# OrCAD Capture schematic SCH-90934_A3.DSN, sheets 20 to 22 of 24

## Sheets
20 C-06 CPU IO/PHY: size C
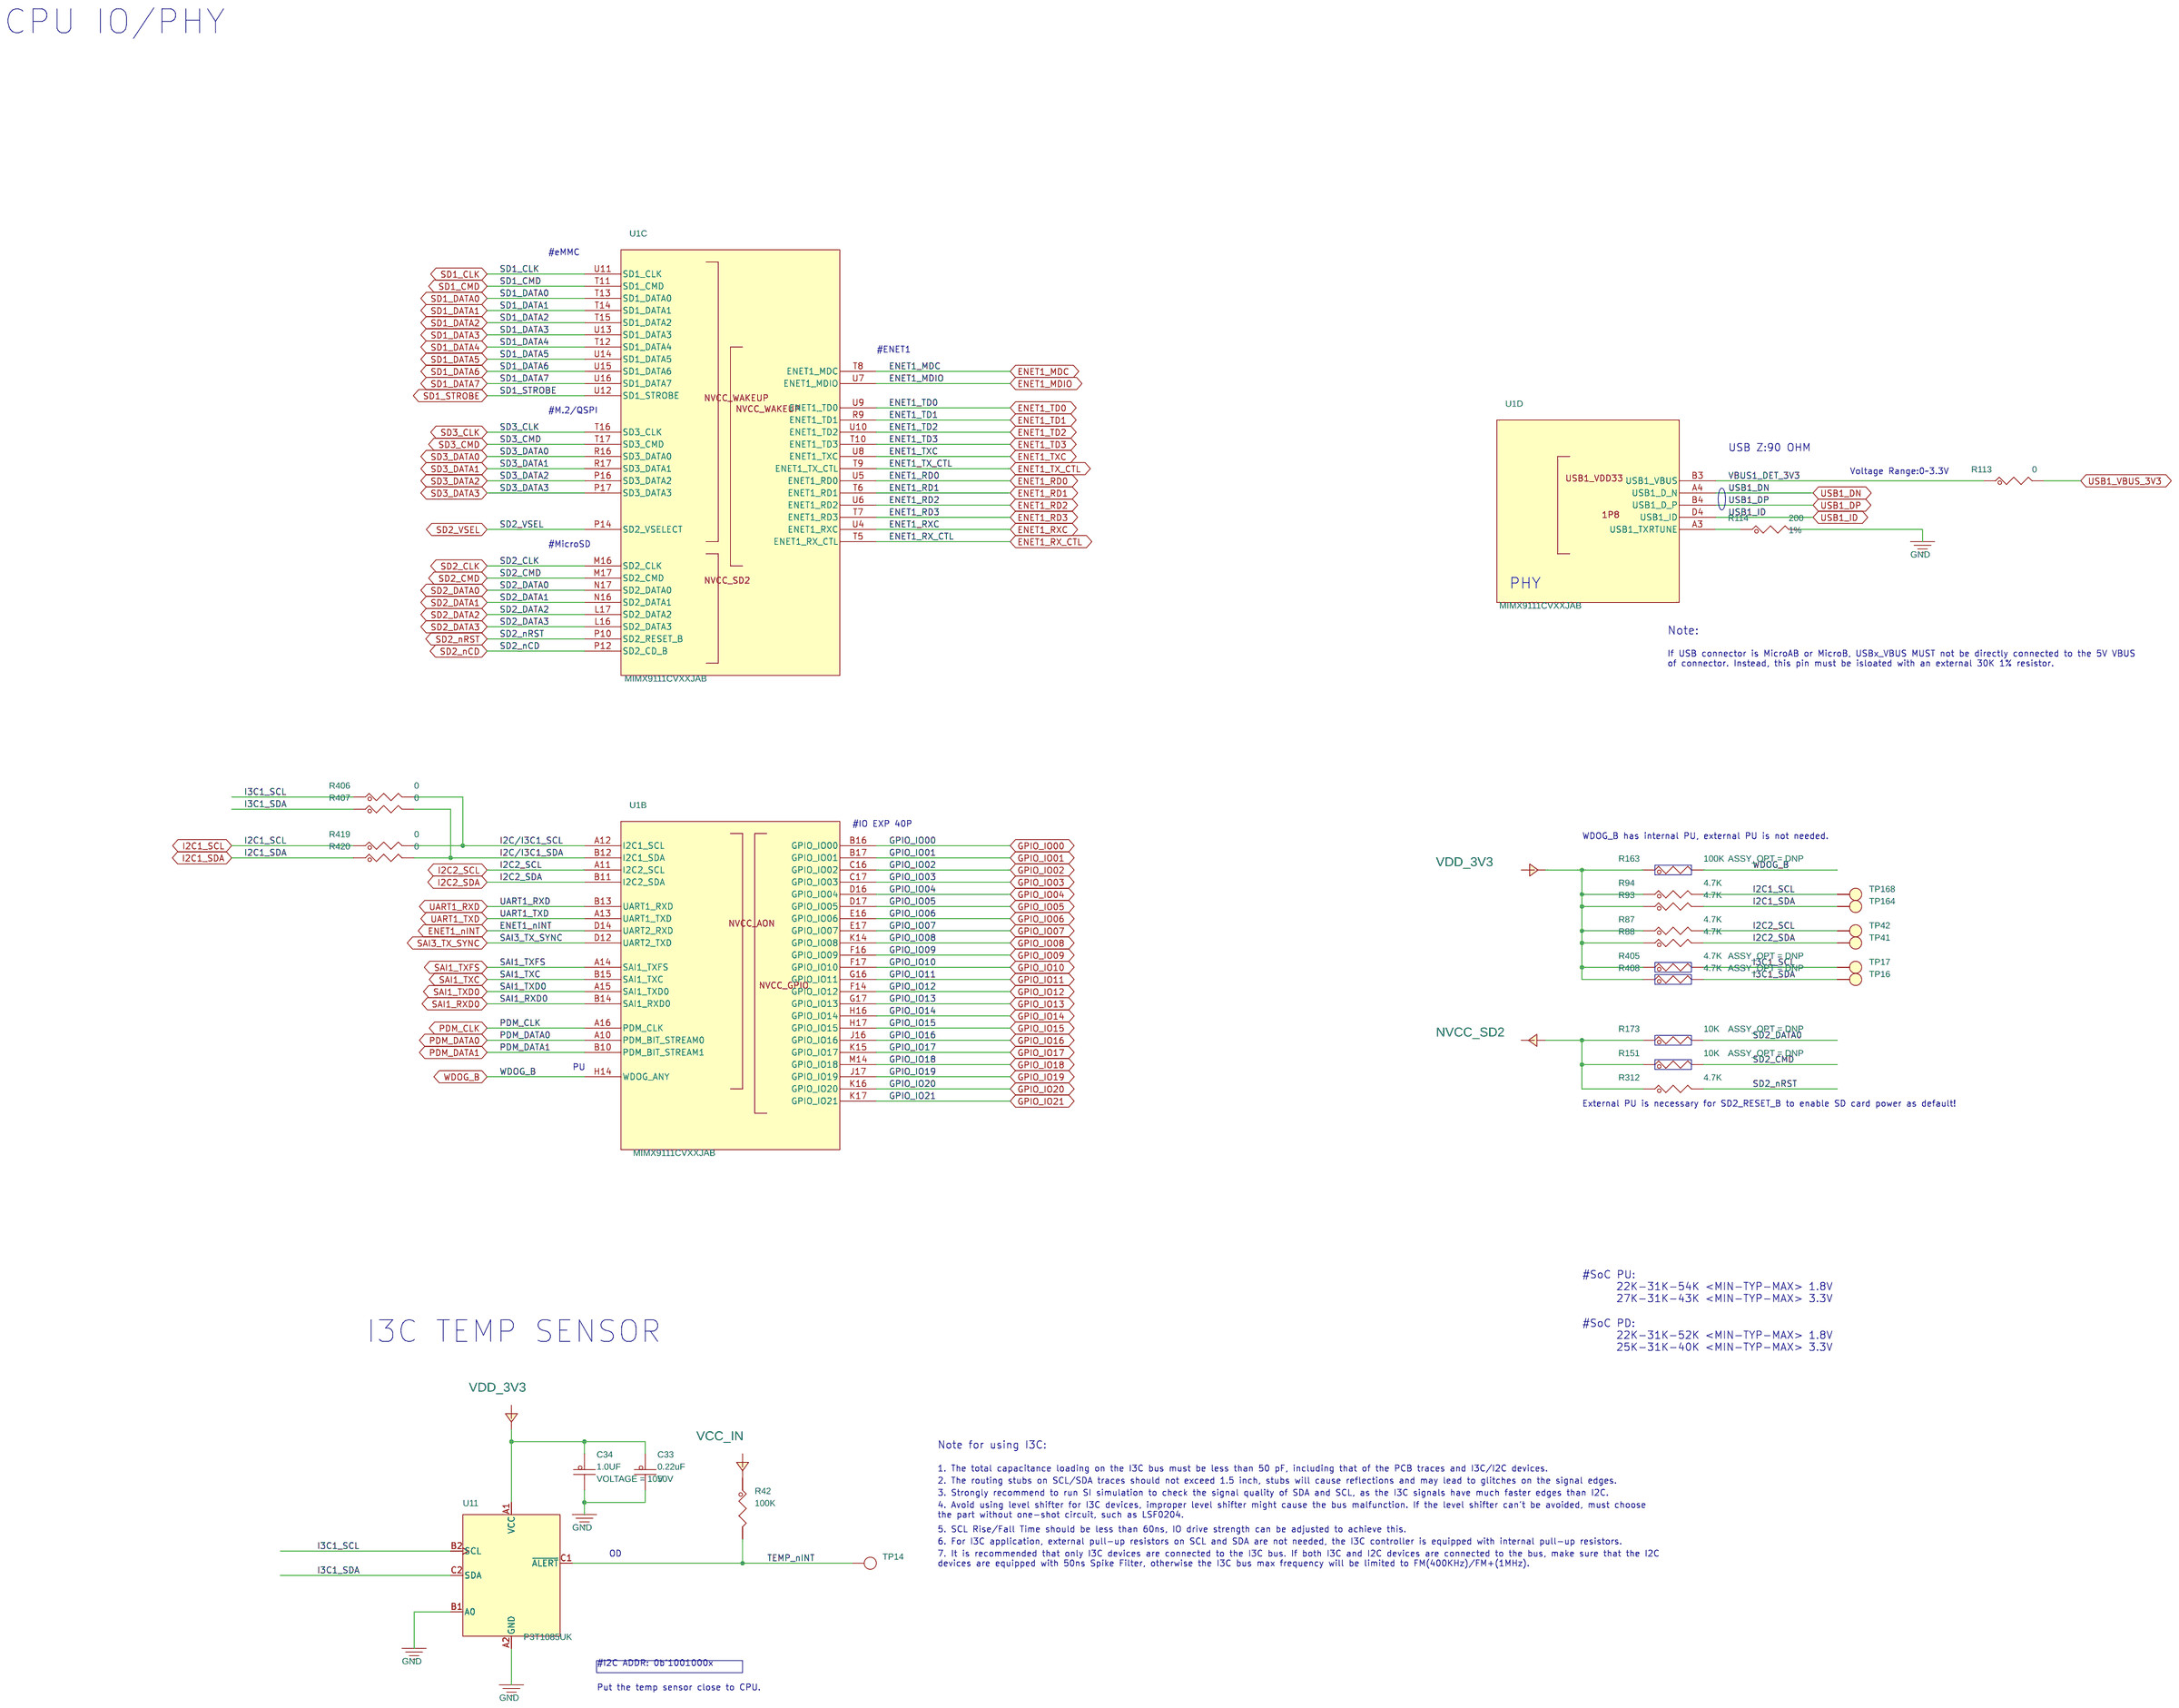
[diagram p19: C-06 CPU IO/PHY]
21 C-17 CAN/Ext RTC: size A3
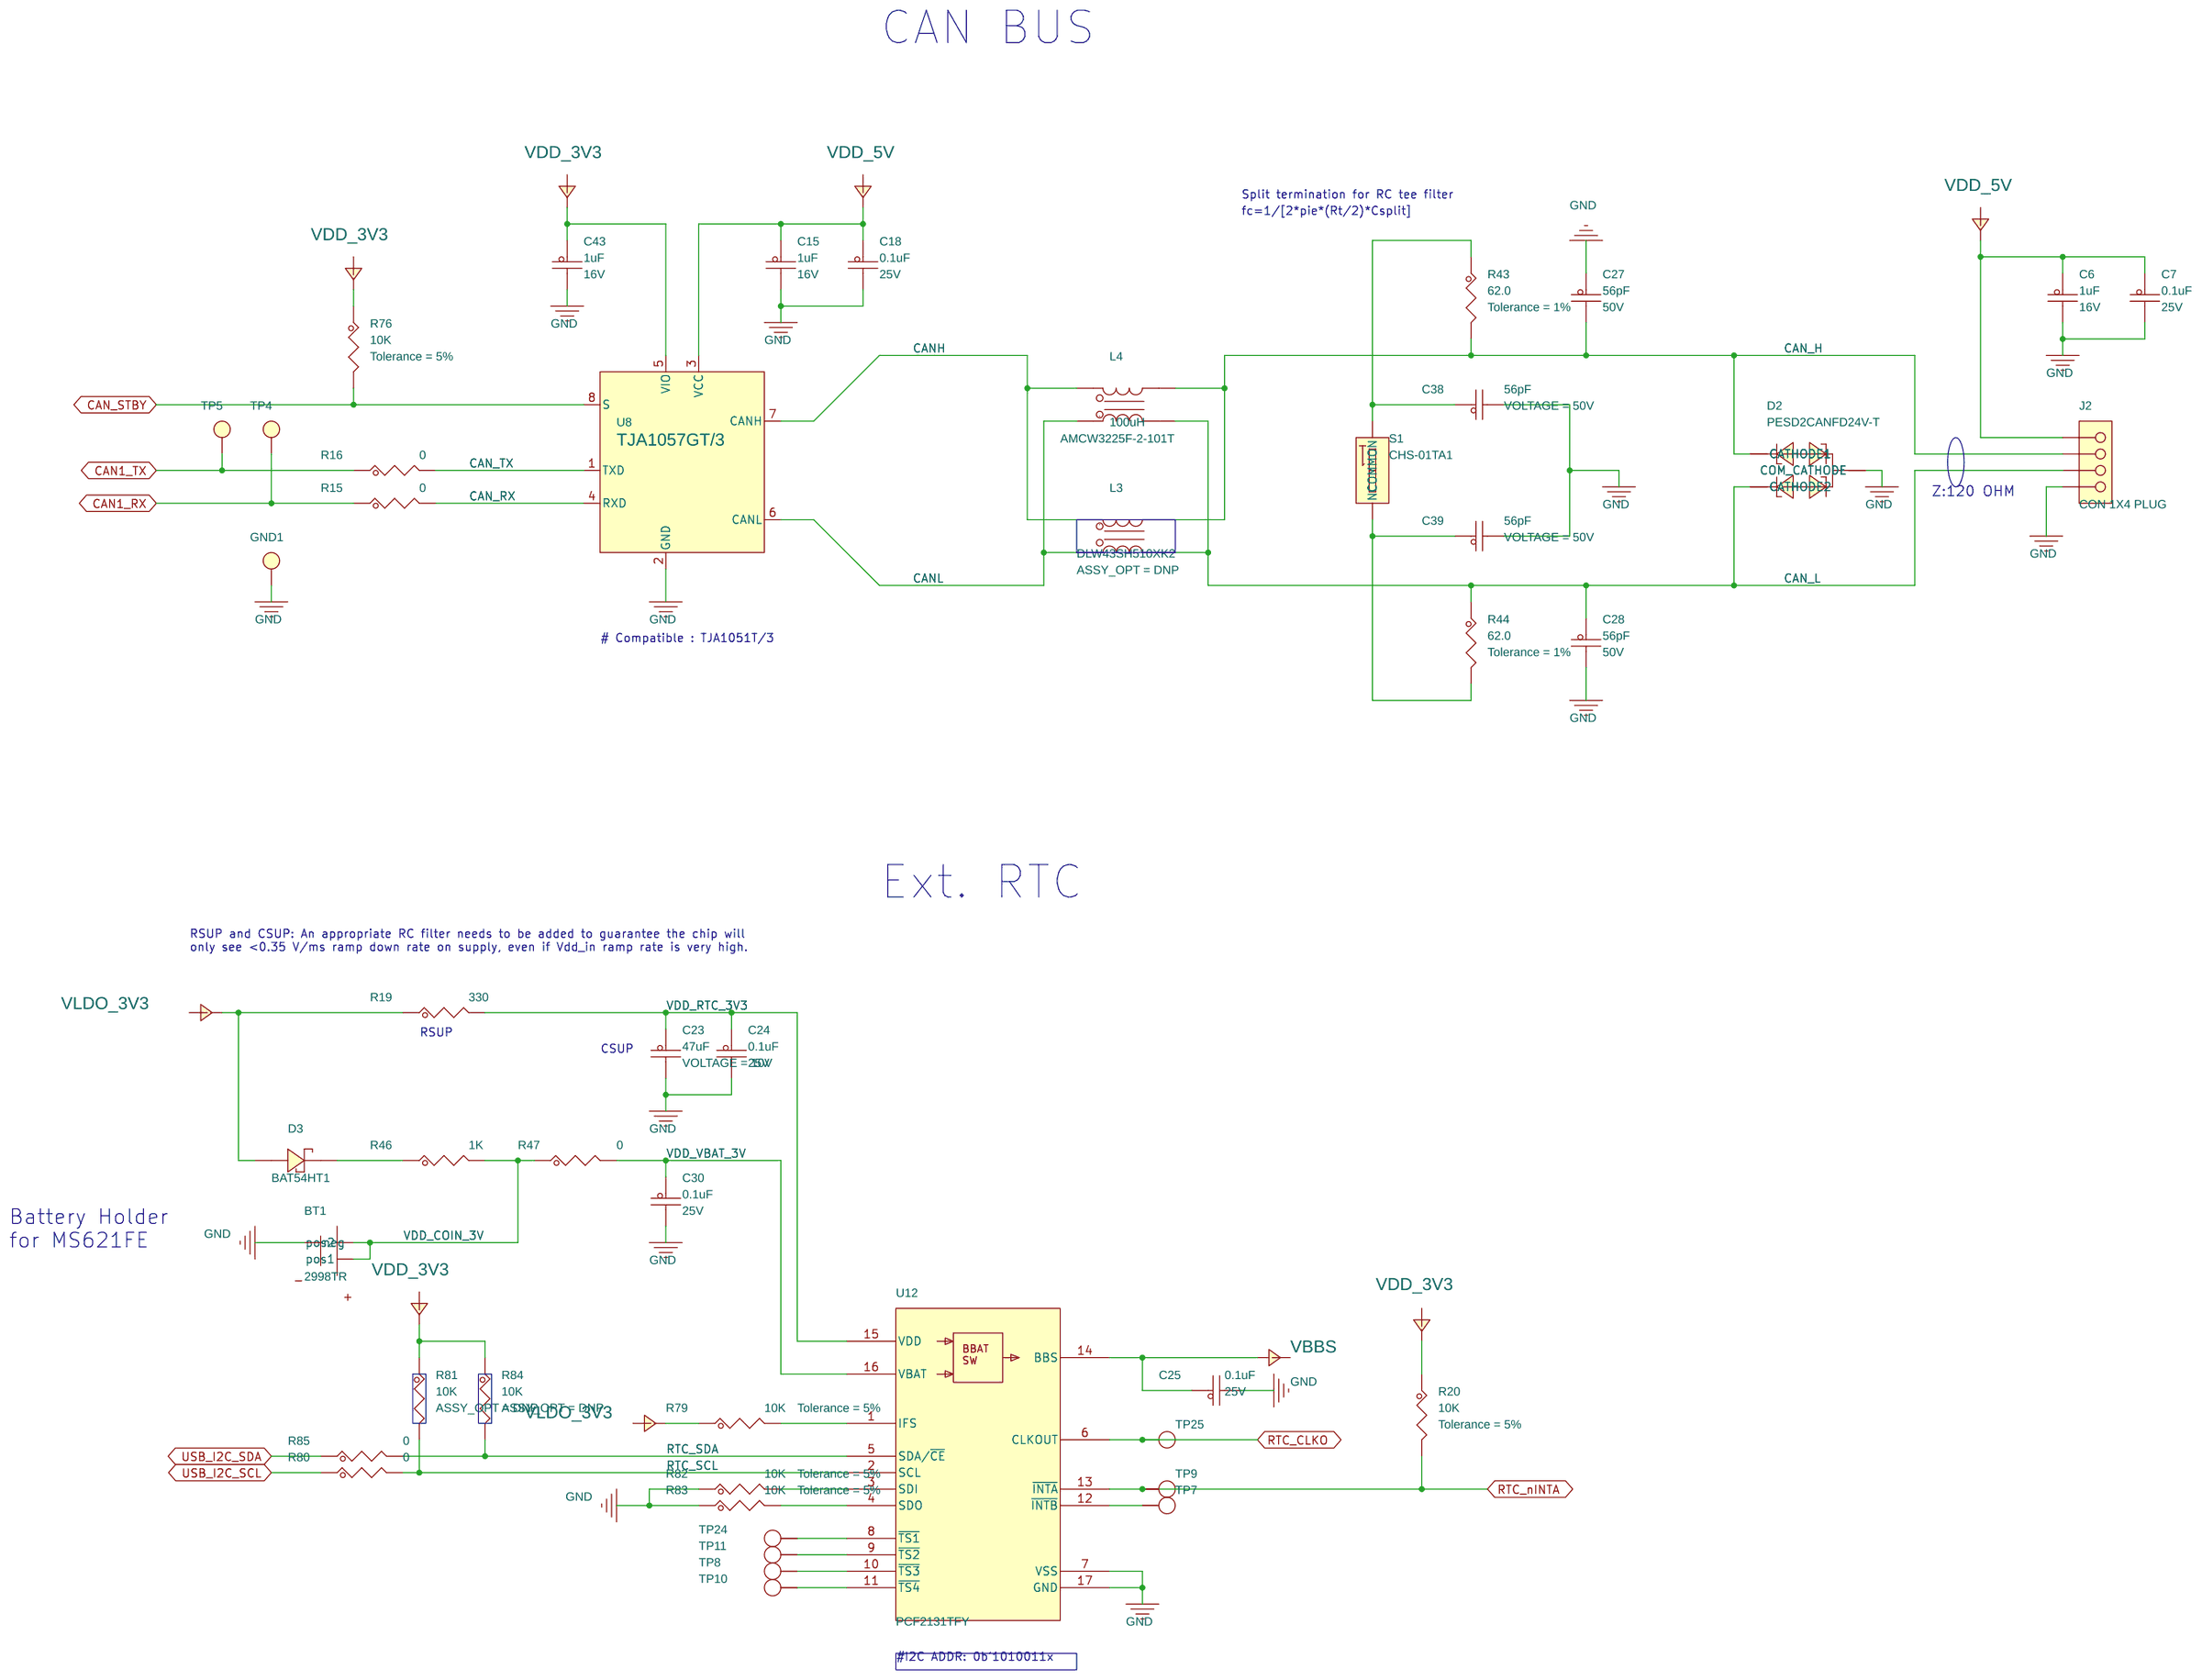
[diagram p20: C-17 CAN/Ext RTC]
22 C-15 M.2 WIFI/BT: size C
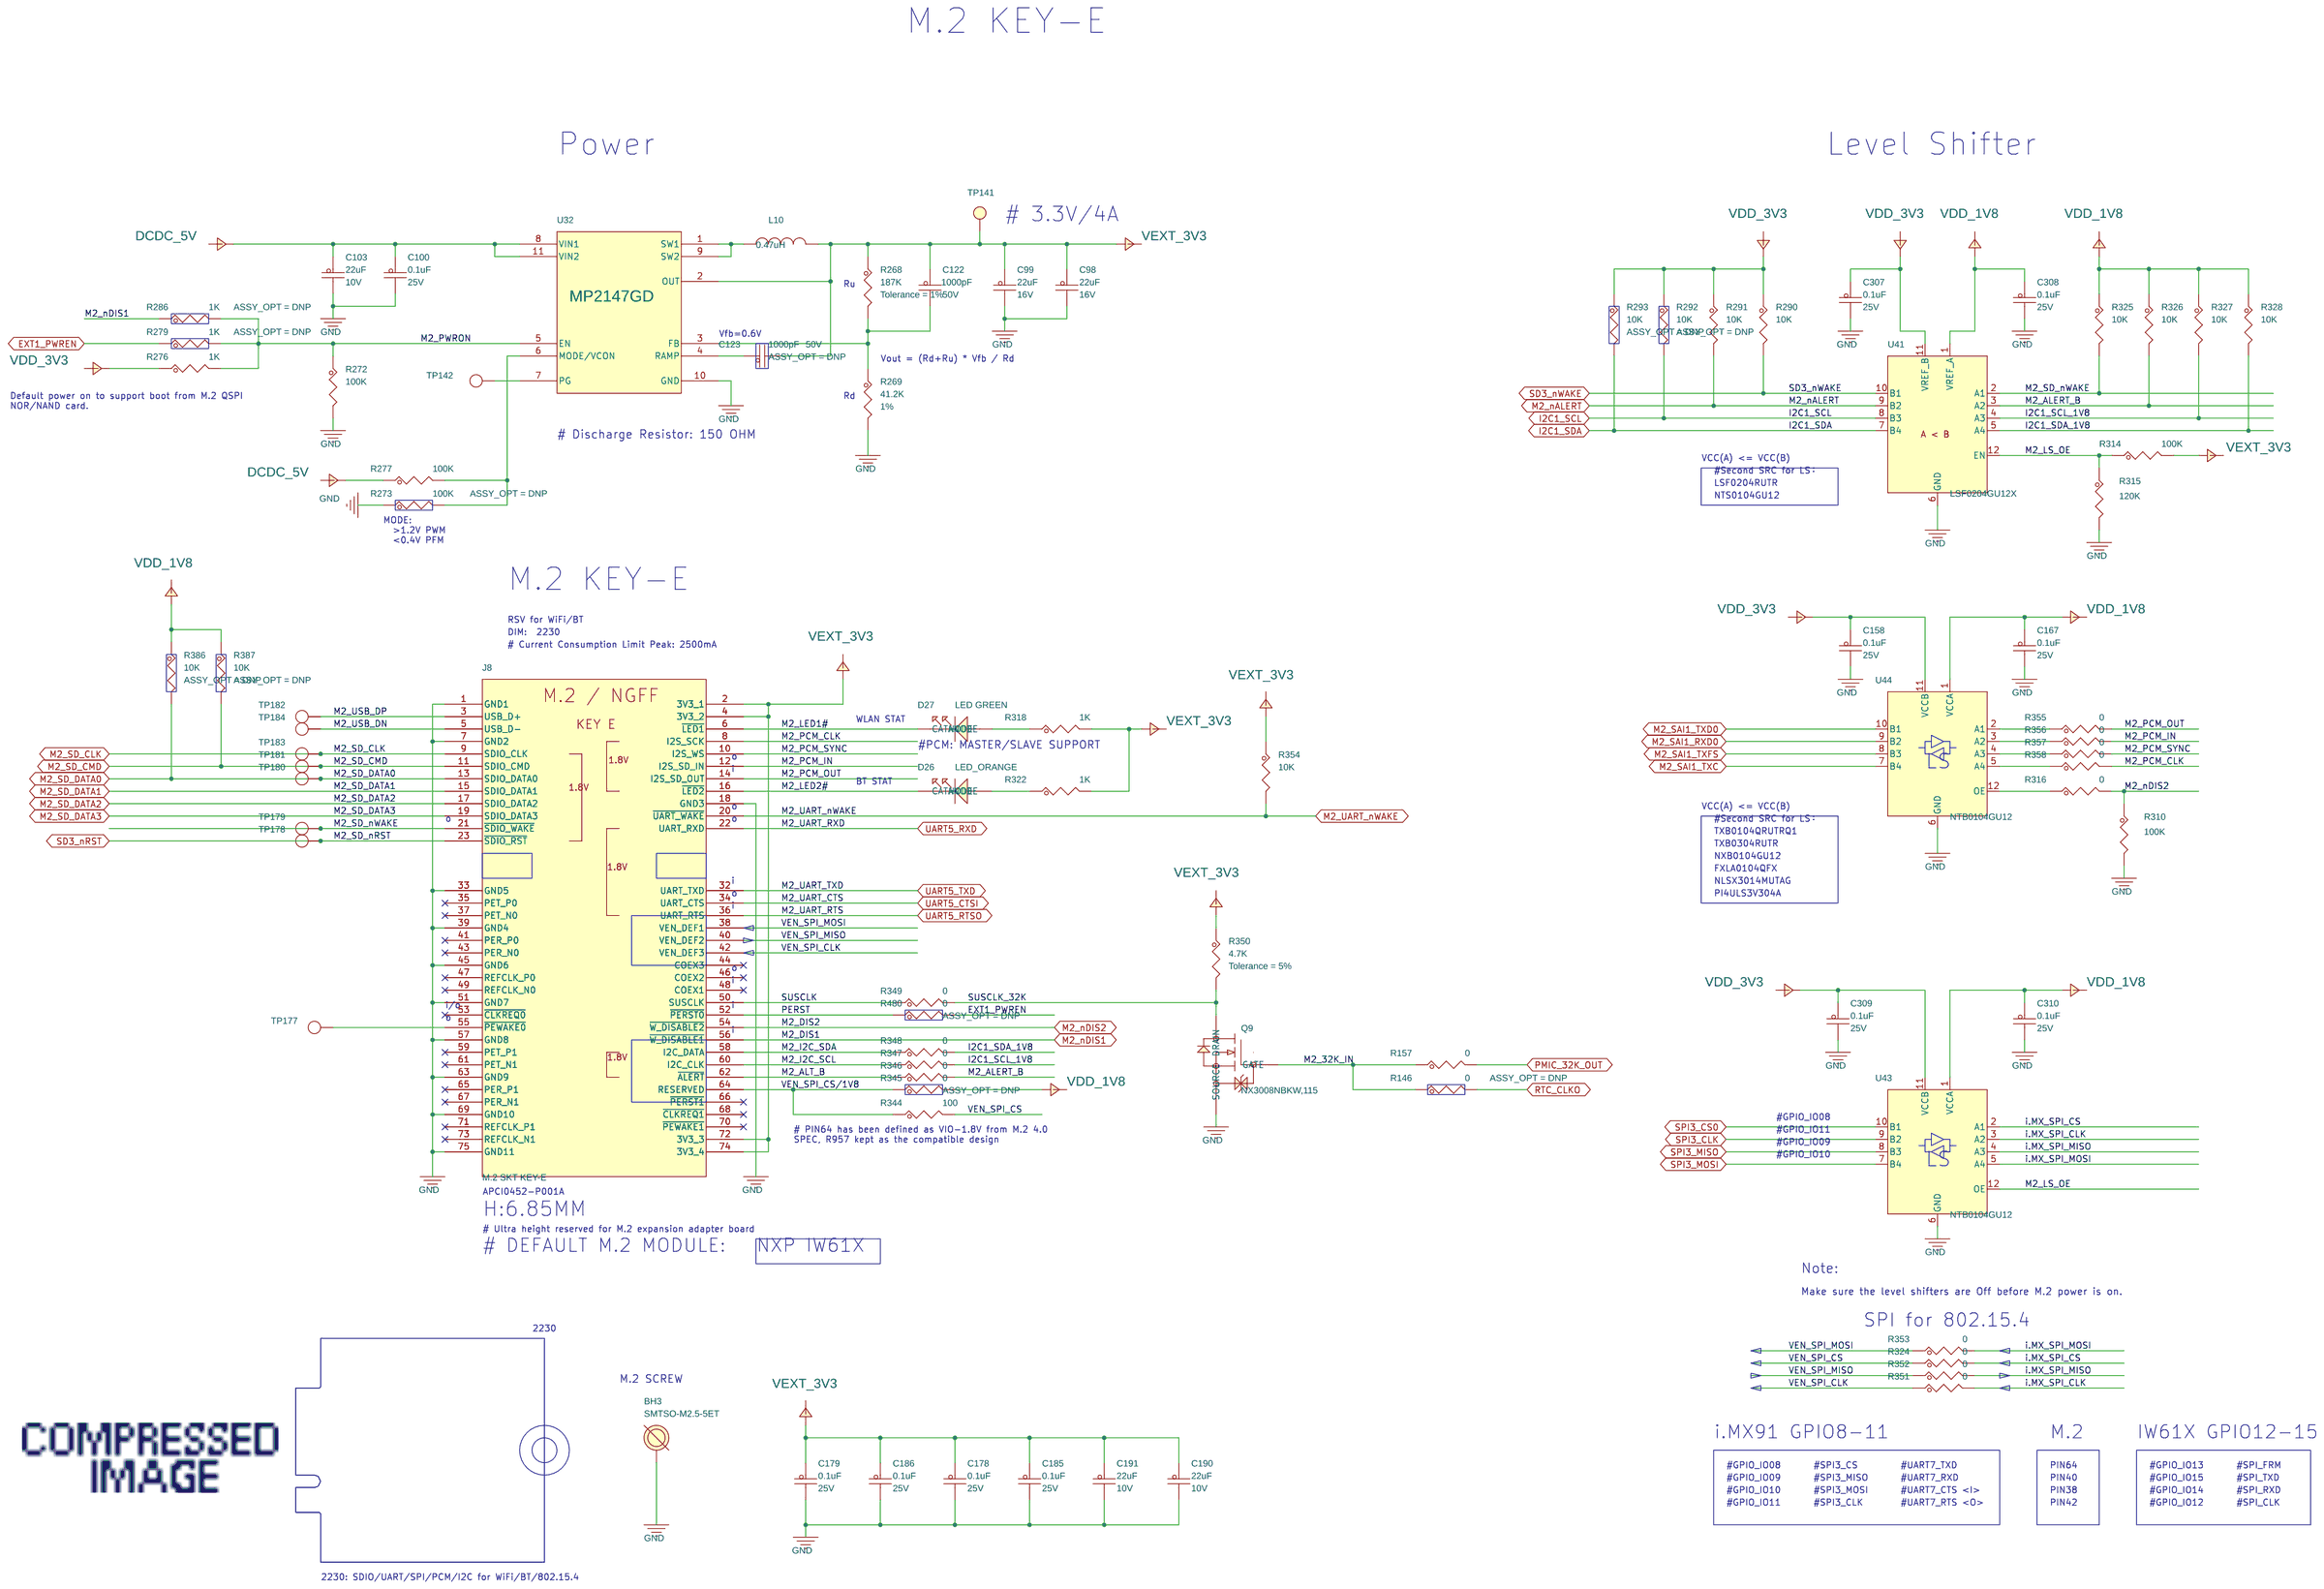
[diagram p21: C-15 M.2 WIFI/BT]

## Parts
sheet C-06 CPU IO/PHY
C33  0.22uF  [CC0402_25]
C34  1.0UF  [CC0402_25]
R42  100K  [0402_CC]
R87  4.7K  [0402_CC]
R88  4.7K  [0402_CC]
R93  4.7K  [0402_CC]
R94  4.7K  [0402_CC]
R113  0  [0201_CC]
R114  200  [0201_CC]
R151  10K  [0402_CC]
R163  100K  [0402_CC]
R173  10K  [0402_CC]
R312  4.7K  [0402_CC]
R405  4.7K  [0402_CC]
R406  0  [RC0402_25]
R407  0  [RC0402_25]
R408  4.7K  [0402_CC]
R419  0  [RC0402_25]
R420  0  [RC0402_25]
TP14  TPAD_020  [tpad_020]
TP16  TP_35MIL  [testpoint_35mil]
TP17  TP_35MIL  [testpoint_35mil]
TP41  TP_35MIL  [testpoint_35mil]
TP42  TP_35MIL  [testpoint_35mil]
TP164  TP_35MIL  [testpoint_35mil]
TP168  TP_35MIL  [testpoint_35mil]
U11  P3T1085UK  [wlcsp6_0p4_0p84x1p18]
sheet C-07 CPU MISC
U1  MIMX9111CVXXJAB  [pbga208_0p5_9x9mm_sm]  (sections A,B,C,D,E,F)
sheet C-15 M.2 WIFI/BT
BH3  SMTSO-M2.5-5ET  [mh244-166t_202h]
C98  22uF  [CC0805_OV]
C99  22uF  [CC0805_OV]
C100  0.1uF  [CC0402_25]
C103  22uF  [CC0603]
C122  1000pF  [CC0402_25]
C123  1000pF  [CC0402_25]
C158  0.1uF  [CC0402_25]
C167  0.1uF  [CC0402_25]
C178  0.1uF  [CC0402_25]
C179  0.1uF  [CC0402_25]
C185  0.1uF  [CC0402_25]
C186  0.1uF  [CC0402_25]
C190  22uF  [CC0603]
C191  22uF  [CC0603]
C307  0.1uF  [CC0402_25]
C308  0.1uF  [CC0402_25]
C309  0.1uF  [CC0402_25]
C310  0.1uF  [CC0402_25]
D26  LED_ORANGE  [led_0603_11mil]
D27  LED GREEN  [LED_0603]
J8  M.2 SKT KEY-E  [con67_0p5_type-e_22x7p3_ra_270h]
L10  0.47uH  [ind_sph2520]
Q9  NX3008NBKW,115  [sc70_3]
R146  0  [0402_CC]
R157  0  [0402_CC]
R268  187K  [0402_CC]
R269  41.2K  [RC0402_25]
R272  100K  [0402_CC]
R273  100K  [0402_CC]
R276  1K  [0402_CC]
R277  100K  [0402_CC]
R279  1K  [0402_CC]
R286  1K  [0402_CC]
R290  10K  [0402_CC]
R291  10K  [0402_CC]
R292  10K  [0402_CC]
R293  10K  [0402_CC]
R310  100K  [0402_CC]
R314  100K  [0402_CC]
R315  120K  [0402_CC]
R316  0  [0402_CC]
R318  1K  [0402_CC]
R322  1K  [0402_CC]
R324  0  [0402_CC]
R325  10K  [0402_CC]
R326  10K  [0402_CC]
R327  10K  [0402_CC]
R328  10K  [0402_CC]
R344  100  [RC0402_25]
R345  0  [0402_CC]
R346  0  [0402_CC]
R347  0  [0402_CC]
R348  0  [0402_CC]
R349  0  [0402_CC]
R350  4.7K  [RC0402_25]
R351  0  [0402_CC]
R352  0  [0402_CC]
R353  0  [0402_CC]
R354  10K  [0402_CC]
R355  0  [0402_CC]
R356  0  [0402_CC]
R357  0  [0402_CC]
R358  0  [0402_CC]
R386  10K  [0402_CC]
R387  10K  [0402_CC]
R480  0  [0402_CC]
TP141  TP_35MIL  [testpoint_35mil]
TP142  TPAD_020  [tpad_020]
TP177  TPAD_020  [tpad_020]
TP178  TPAD_020  [tpad_020]
TP179  TPAD_020  [tpad_020]
TP180  TPAD_020  [tpad_020]
TP181  TPAD_020  [tpad_020]
TP182  TPAD_020  [tpad_020]
TP183  TPAD_020  [tpad_020]
TP184  TPAD_020  [tpad_020]
U32  MP2147GD  [qfn12_0p5_2x3mm_ep]
U41  LSF0204GU12X  [uqfn12_1p7x2mm]
U43  NTB0104GU12  [xqfn12_0p4_1p8x2p1]
U44  NTB0104GU12  [xqfn12_0p4_1p8x2p1]
sheet C-17 CAN/Ext RTC
BT1  2998TR  [batt_6p8mm_sm]
C6  1uF  [CC0402_25]
C7  0.1uF  [CC0402_25]
C15  1uF  [CC0402_25]
C18  0.1uF  [CC0402_25]
C23  47uF  [0805_CC]
C24  0.1uF  [CC0402_25]
C25  0.1uF  [CC0402_25]
C27  56pF  [CC0402_25]
C28  56pF  [CC0402_25]
C30  0.1uF  [CC0402_25]
C38  56pF  [CC0402_25]
C39  56pF  [CC0402_25]
C43  1uF  [CC0402_25]
D2  PESD2CANFD24V-T  [sot23_a]
D3  BAT54HT1  [SOD323]
GND1  TP_35MIL  [testpoint_35mil]
J2  CON 1X4 PLUG  [con1x4_2mm_th_303h]
L3  DLW43SH510XK2  [IND_DLW43]
L4  100uH  [ind4_amcw3225_smt]
R15  0  [0402_CC]
R16  0  [0402_CC]
R19  330  [RC0402_25]
R20  10K  [0402_CC]
R43  62.0  [0603_CC]
R44  62.0  [0603_CC]
R46  1K  [0402_CC]
R47  0  [0402_CC]
R76  10K  [0402_CC]
R79  10K  [0402_CC]
R80  0  [0402_CC]
R81  10K  [0402_CC]
R82  10K  [0402_CC]
R83  10K  [0402_CC]
R84  10K  [0402_CC]
R85  0  [0402_CC]
S1  CHS-01TA1  [sw_2p8x5p7_sm]
TP4  TP_35MIL  [testpoint_35mil]
TP5  TP_35MIL  [testpoint_35mil]
TP7  TPAD_020  [tpad_020]
TP8  TPAD_020  [tpad_020]
TP9  TPAD_020  [tpad_020]
TP10  TPAD_020  [tpad_020]
TP11  TPAD_020  [tpad_020]
TP24  TPAD_020  [tpad_020]
TP25  TPAD_020  [tpad_020]
U8  TJA1057GT/3  [SO8_1P27_4X5]
U12  PCF2131TFY  [so16_0p5_3p5x4p5_mm]

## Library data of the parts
C33 = CAP_NP: CAP CER 0.22uF 50V 10% X5R 0402; AGILE_PN: 150-79999; CAD_APPROVED: Yes; FPLIST: CC0402_25,CC0402_HD,0402_CC; HEIGHT: 0.55MM; MFG_NAME01: TAIYO YUDEN; MFG_PN01: UMK105BJ224KV-F; Package Size: 0402; ROHS: Yes; Rated Voltage: 50V; Temp Range: -55C to +85C; Temp_Range: -55°C to +85°C; Tolerance: 10%; VOLTAGE: 50V
C34 = CAP_NP: CAP CER 1.0UF 10V 10% X5R 0402; AGILE_PN: 150-75772; CAD_APPROVED: Yes; FPLIST: CC0402_25,CC0402_HD,0402_CC; HEIGHT: 0.6MM; MFG_NAME01: YAGEO AMERICA; MFG_PN01: CC0402KRX5R6BB105; Package Size: 0402; ROHS: Yes; Rated Voltage: 10V; SIGNAL_MODEL: DEFAULT_CAPACITOR_1e+06pF_2_1; TOL: 10%; Temp Range: -55C to +85C; Tolerance: 10%; VOLTAGE: 10V; voltage rating: 10V
R42 = RES: RES MF 100K 1/16W 5% 0402; AGILE_PN: 470-75597; CAD_APPROVED: Yes; FPLIST: RC0402_25,RC0402_HD,0402_CC; HEIGHT: 0.40 MM; MFG_NAME01: VENKEL COMPANY; MFG_PN01: CR0402-16W-104JT; ROHS: Yes; Temp Range: -55C to +155C; Tolerance: 5%; VOLTAGE: 50V
R87 R88 R93 R94 R312 = RES: RES MF 4.7K 1/10W 5% AEC-Q200 0402; AGILE_PN: 470-82064; CAD_APPROVED: Yes; FPLIST: RC0402_25,RC0402_HD,0402_CC,RC0402_X2; HEIGHT: 0.41mm; MFG_NAME01: KOA SPEER; MFG_PN01: RK73B1ETTP472J; ROHS: Yes; Temp Range: -55C to +155C; Temp_Range: -55C to +155C; Tolerance: 5%; VOLTAGE: 50V
R113 = RES: RES MF ZERO OHM 1/20W -- 0201; AGILE_PN: 470-76631; CAD_APPROVED: Yes; FPLIST: RC0201,0201_CC,RC0201_X2; HEIGHT: 0.30 MM; MFG_NAME01: BOURNS; MFG_PN01: CR0201-J/-000GLF; ROHS: Yes
R114 = RES: RES MF 200 OHM 1/20W 1% 0201; AGILE_PN: 470-82323; CAD_APPROVED: Yes; FPLIST: RC0201,0201_CC; HEIGHT: 0.26MM; MFG_NAME01: YAGEO AMERICA; MFG_PN01: RC0201FR-07200RL; ROHS: Yes; Temp Range: -55°C ~ 125°C; Temp_Range: -55°C ~ 125°C; Tolerance: 1%; VOLTAGE: 25V
R81 R84 R151 R173 R292 R293 R386 R387 = RES: RES MF 10K 1/16W 5% 0402; AGILE_PN: 470-75557; ASSY_OPT: DNP; CAD_APPROVED: Yes; FPLIST: RC0402_25,RC0402_HD,0402_CC; HEIGHT: 0.4 MM; MFG_NAME01: VISHAY INTERTECHNOLOGY; MFG_PN01: CRCW040210K0JNED; ROHS: Yes; Tolerance: 5%
R163 = RES: RES MF 100K 1/16W 5% 0402; AGILE_PN: 470-75597; ASSY_OPT: DNP; CAD_APPROVED: Yes; FPLIST: RC0402_25,RC0402_HD,0402_CC; HEIGHT: 0.40 MM; MFG_NAME01: VENKEL COMPANY; MFG_PN01: CR0402-16W-104JT; ROHS: Yes; Temp Range: -55C to +155C; Tolerance: 5%; VOLTAGE: 50V
R405 R408 = RES: RES MF 4.7K 1/10W 5% AEC-Q200 0402; AGILE_PN: 470-82064; ASSY_OPT: DNP; CAD_APPROVED: Yes; FPLIST: RC0402_25,RC0402_HD,0402_CC,RC0402_X2; HEIGHT: 0.41mm; MFG_NAME01: KOA SPEER; MFG_PN01: RK73B1ETTP472J; ROHS: Yes; Temp Range: -55C to +155C; Temp_Range: -55C to +155C; Tolerance: 5%; VOLTAGE: 50V
R47 R80 R85 R157 R316 R324 R346-R349 R351-R353 R355-R358 R406 R407 R419 R420 = RES: RES MF ZERO OHM 1/16W 5% 0402; AGILE_PN: 470-75394; CAD_APPROVED: Yes; FPLIST: RC0402_25,RC0402_HD,RC0402_X2,0402_CC; HEIGHT: 0.45; MFG_NAME01: YAGEO AMERICA; MFG_PN01: RC0402JR-070RL; ROHS: Yes; Temp Range: -55 to +155C; Tolerance: 5%; VOLTAGE: 1/16W
TP7-TP11 TP14 TP24 TP25 TP142 TP177-TP184 = TESTLOOP: TEST POINT PAD 0.5MM DIA SMT, NO PART TO ORDER; AGILE_PN: 211-77484; ASSY_OPT: DNP; CAD_APPROVED: Yes; HEIGHT: 0.1MM; ROHS: Yes
GND1 TP4 TP5 TP16 TP17 TP41 TP42 TP141 TP164 TP168 = T_POINT_R: TEST POINT PAD .035 SMT, no part to order; AGILE_PN: 510-75618; ASSY_OPT: DNP; CAD_APPROVED: Yes; HEIGHT: 0.1MM; ROHS: Yes
U11 = P3T2108_6P: IC DIG TEMP SENSOR 12BIT I3C/I2C 12.5MHz/3.4MHz 1.4-3.6V WLCSP6; 3D_Mechanical_Footprint_File: http://fcl.am.freescale.net/ALLEGRO/step/wlcsp6_0p4_0p84x1p18.STEP; AGILE_PN: TMP-CIP-12138; HEIGHT: 0.485MM; MFG_NAME01: NXP SEMICONDUCTORS; MFG_PN01: P3T1085UKZ; PRE_APN: 312-83691; ROHS: Yes; Temp Range: -40°C to +125°C; VOLTAGE: 1.4-3.6V
U1 = MIMX9122DVXxLAA_BGA208_A: IC CPU SINGLE CORTEX A55 1.4GHz -- FCPBGA208; 3D_Mechanical_Footprint_File: http://fcl.am.freescale.net/ALLEGRO/step/pbga208_0p5_9x9mm_sm.STEP; AGILE_PN: 330-10031; CAD_APPROVED: Yes; HEIGHT: 1mm; MFG_NAME01: NXP SEMICONDUCTOR; Package Size: FCPBGA208; ROHS: NULL; Temp Range: -40  °C to +105 °C
BH3 = MOUNT_HOLE: FASTENER, STANDOFF M2.5 ROUND FEMALE OD CS L5.13MM; AGILE_PN: 280-77749; CAD_APPROVED: Yes; HEIGHT: 5.13MM; MFG_NAME01: SHENZHEN SINHOO SCIENCE TECHNOLOGY DEVELOPMENT CO.,LTD; ROHS: Yes
C98 C99 = CAP_NP: CAP CER 22UF 16V 20% X5R 0805; 3D_Mechanical_Footprint_File: http://fcl.am.freescale.net/ALLEGRO/step/cc0805_ov.STEP; AGILE_PN: 150-81221; CAD_APPROVED: Yes; FPLIST: CC0805_OV,CC0805,0805_CC; HEIGHT: 1.45MM; MFG_NAME01: TDK Corporation; MFG_PN01: C2012X5R1C226M125AC; Package Size: 0805 (2012 Metric); ROHS: Yes; Rated Voltage: 16V; Temp Range: -55C to +85C; Tolerance: 20%; VOLTAGE: 16V
C7 C18 C24 C30 C100 C158 C167 C178 C179 C185 C186 C307-C310 = CAP_NP: CAP CER 0.1UF 25V 10% X5R 0402; AGILE_PN: 150-78633; CAD_APPROVED: Yes; FPLIST: CC0402_25,CC0402_HD,0402_CC,capc0402_l; HEIGHT: 0.55MM; MFG_NAME01: YAGEO AMERICA; MFG_PN01: CC0402KRX5R8BB104; Package Size: 0402; ROHS: Yes; Rated Voltage: 25V; Temp Range: -55C to +85C; Tolerance: 10%; VOLTAGE: 25V
C103 C190 C191 = CAP_NP: CAP CER 22uF 10V 20% X5R 0603; AGILE_PN: 150-79530; CAD_APPROVED: Yes; FPLIST: CC0603_OV,CC0603,0603_cc_tol; HEIGHT: 1MM; MFG_NAME01: SAMSUNG; MFG_PN01: CL10A226MP7LUNC; Package Size: 0603; ROHS: Yes; Rated Voltage: 10V; SIGNAL_MODEL: DEFAULT_CAPACITOR_2.2e+07pF_2_1; Temp Range: -55C to +85C; Tolerance: 20%; VOLTAGE: 10V; WVDC: 6.3V
C122 = CAP_NP: CAP CER 1000PF 50V 5% C0G 0402; AGILE_PN: 150-76334; CAD_APPROVED: Yes; FPLIST: CC0402_25,CC0402_HD,0402_CC; HEIGHT: 0.55MM; MFG_NAME01: MURATA; MFG_PN01: GRM1555C1H102JA01D; Package Size: 0402; Package Type: 180mm Paper Tape; ROHS: Yes; Rated Voltage: 50V; Temp Range: -55C to +125C; Tolerance: 5%; VOLTAGE: 50V
C123 = CAP_NP: CAP CER 1000PF 50V 5% C0G 0402; AGILE_PN: 150-76334; ASSY_OPT: DNP; CAD_APPROVED: Yes; FPLIST: CC0402_25,CC0402_HD,0402_CC; HEIGHT: 0.55MM; MFG_NAME01: MURATA; MFG_PN01: GRM1555C1H102JA01D; Package Size: 0402; Package Type: 180mm Paper Tape; ROHS: Yes; Rated Voltage: 50V; Temp Range: -55C to +125C; Tolerance: 5%; VOLTAGE: 50V
D26 = LED: LED OR SGL 20MA 0603; 3D_Mechanical_Footprint_File: http://fcl.am.freescale.net/ALLEGRO/step/led_0603_11mil.STEP; AGILE_PN: 370-76572; CAD_APPROVED: Yes; HEIGHT: 0.28; MFG_NAME01: KINGBRIGHT; MFG_PN01: APG1608SEKC/T; ROHS: Yes; Rated Voltage: 2V; Temp Range: -40°C to +85°C; Temp_Range: -40°C to +85°C; VOLTAGE: 2v
D27 = LED: LED GRN SGL 25MA SMT 0603; AGILE_PN: 370-76672; CAD_APPROVED: Yes; HEIGHT: 0.8; MFG_NAME01: DIALIGHT; MFG_PN01: 598-8070-107F; ROHS: Yes; Rated Voltage: 2V; VOLTAGE: 2V
J8 = CON_67_FEMALE_RA_B: CON 67 PCIE M.2 KEY-E RA SMT 0.5MM SP 270H AU; 3D_Mechanical_Footprint_File: http://fcl.am.freescale.net/ALLEGRO/step/con67_0p5_type-e_22x7p3_ra_270h.STEP; AGILE_PN: 211-81337; CAD_APPROVED: Yes; HEIGHT: 6.85; MFG_NAME01: LOTES CO LTD; MFG_PN01: APCI0452-P001A; Package Size: 22.0 x 7.3 x 6.85 mm; Package Type: SMD/SMT; ROHS: Yes
L10 = INDUCTOR: IND PWR 0.47uH@1MHZ 4.7A 20% SMT; AGILE_PN: 180-78647; CAD_APPROVED: Yes; HEIGHT: 1.2; MFG_NAME01: SHENZHEN SUNLORD ELECTRONICS CO., LTD; MFG_PN01: WPN252012ER47MT; PART_TYPE: INDUCTOR\POWER; ROHS: Yes; TOL: 20%; Temp Range: -40°C to +125°C; Temp_Range: -40°C to +125°C; Tolerance: 20%
Q9 = NX3008NBKW_SOT323: TRAN NMOS SW 30V 350mA AEC-Q101 SC-70; 3D_Mechanical_Footprint_File: http://fcl.am.freescale.net/ALLEGRO/step/sc70_3.STEP; AGILE_PN: 480-79736; CAD_APPROVED: Yes; HEIGHT: 1.1; MFG_NAME01: NEXPERIA; ROHS: Yes
R146 R345 R480 = RES: RES MF ZERO OHM 1/16W 5% 0402; AGILE_PN: 470-75394; ASSY_OPT: DNP; CAD_APPROVED: Yes; FPLIST: RC0402_25,RC0402_HD,RC0402_X2,0402_CC; HEIGHT: 0.45; MFG_NAME01: YAGEO AMERICA; MFG_PN01: RC0402JR-070RL; ROHS: Yes; Temp Range: -55 to +155C; Tolerance: 5%; VOLTAGE: 1/16W
R268 = RES: RES MF 187K 1/16W 1% 0402; AGILE_PN: 470-31090; CAD_APPROVED: Yes; FPLIST: RC0402_25,RC0402_HD,0402_CC; HEIGHT: 0.40 MM; MFG_NAME01: WALSIN TECHNOLOGY CORP.; MFG_PN01: WR04X1873FTL; ROHS: Yes; Temp_Range: -55C to +155C; Tolerance: 1%
R269 = RES: RES MF 41.2K 1/10W 1% AEC-Q200 0402; AGILE_PN: 470-81721; CAD_APPROVED: Yes; FPLIST: RC0402_25,RC0402_HD,0402_CC; HEIGHT: 0.40 MM; MFG_NAME01: KOA SPEER; MFG_PN01: RK73H1ETTP4122F; ROHS: Yes; Temp_Range: -55C to +155C; Tolerance: 1%
R272 R277 R310 R314 = RES: RES MF 100K 1/16W 5% 0402; AGILE_PN: 470-75597; CAD_APPROVED: Yes; FPLIST: RC0402_25,RC0402_HD,0402_CC; HEIGHT: 0.40 MM; MFG_NAME01: VENKEL COMPANY; MFG_PN01: CR0402-16W-104JT; ROHS: Yes; Temp Range: -55C to +155C; Temp_Range: -55C to +155C; Tolerance: 5%; VOLTAGE: 50V
R273 = RES: RES MF 100K 1/16W 5% 0402; AGILE_PN: 470-75597; ASSY_OPT: DNP; CAD_APPROVED: Yes; FPLIST: RC0402_25,RC0402_HD,0402_CC; HEIGHT: 0.40 MM; MFG_NAME01: VENKEL COMPANY; MFG_PN01: CR0402-16W-104JT; ROHS: Yes; Temp Range: -55C to +155C; Temp_Range: -55C to +155C; Tolerance: 5%; VOLTAGE: 50V
R276 R318 R322 = RES: RES MF 1.0K 1/16W 5% 0402; AGILE_PN: 470-75555; CAD_APPROVED: Yes; FPLIST: RC0402_25,RC0402_HD,RC0402_X2,0402_CC,CAPC0402_L; HEIGHT: 0.41mm; MFG_NAME01: VISHAY INTERTECHNOLOGY; MFG_PN01: CRCW04021K00JNED; ROHS: Yes; Tolerance: 5%
R279 R286 = RES: RES MF 1.0K 1/16W 5% 0402; AGILE_PN: 470-75555; ASSY_OPT: DNP; CAD_APPROVED: Yes; FPLIST: RC0402_25,RC0402_HD,RC0402_X2,0402_CC,CAPC0402_L; HEIGHT: 0.41mm; MFG_NAME01: VISHAY INTERTECHNOLOGY; MFG_PN01: CRCW04021K00JNED; ROHS: Yes; Tolerance: 5%
R20 R76 R79 R82 R83 R290 R291 R325-R328 R354 = RES: RES MF 10K 1/16W 5% 0402; AGILE_PN: 470-75557; CAD_APPROVED: Yes; FPLIST: RC0402_25,RC0402_HD,0402_CC; HEIGHT: 0.4 MM; MFG_NAME01: VISHAY INTERTECHNOLOGY; MFG_PN01: CRCW040210K0JNED; ROHS: Yes; Tolerance: 5%
R315 = RES: RES MF 120K 1/10W 1% AEC-Q200 0402; AGILE_PN: 470-31069; CAD_APPROVED: Yes; FPLIST: RC0402_25,RC0402_HD,0402_CC; HEIGHT: 0.40 MM; MFG_NAME01: KOA SPEER; MFG_PN01: RK73H1ETTP1203F; ROHS: Yes; Temp Range: -55C to +155C; Tolerance: 1%
R344 = RES: RES MF 100 OHM 1/16W 5% 0402; AGILE_PN: 470-82142; CAD_APPROVED: Yes; FPLIST: RC0402_25,RC0402_HD,RC0402_X2,0402_CC; HEIGHT: 0.45MM; MFG_NAME01: SMEC; MFG_PN01: RC73L2Z101JTF; ROHS: Yes; Temp Range: -55°C to +175°C; Tolerance: 5%
R350 = RES: RES MF 4.7K 1/16W 5% 0402; AGILE_PN: 470-75626; CAD_APPROVED: Yes; FPLIST: RC0402_25,RC0402_HD,0402_CC,RC0402_X2; HEIGHT: 0.41mm; MFG_NAME01: NIC COMPONENTS CORP; MFG_PN01: NRCL04J472TRF; ROHS: Yes; Tolerance: 5%
U32 = MP2147GD_QFN_11P: IC VREG BUCK 0.6V-5.5V 4A 2.8--5.5V QFN12; 3D_Mechanical_Footprint_File: http://fcl.am.freescale.net/ALLEGRO/step/qfn12_0p5_2x3mm_ep.step; AGILE_PN: 315-80523; CAD_APPROVED: Yes; HEIGHT: 1; MFG_NAME01: MONOLITHIC POWER SYSTEMS; ROHS: Yes; VOLTAGE: 2.8-5.6V
U41 = LSF0204_QFN_12P: IC VXLTR BIDIR 4BIT 5V XQFN12; 3D_Mechanical_Footprint_File: http://fcl.am.freescale.net/ALLEGRO/step/xqfn12_0p4_1p8x2p1.step; AGILE_PN: 312-83664; CAD_APPROVED: Yes; FPLIST: uqfn12_1p7x2mm,xqfn12_0p4_1p8x2p1; HEIGHT: 0.5; MFG_NAME01: NEXPERIA; Package Size: XQFN; ROHS: Yes; Supply Voltage: 5 V; Temp Range: -40  °C to +125 °C; VOLTAGE: 5V
U43 U44 = NTB0104GU12_12P: IC DUAL VXLTR XCVR 4BIT 1.2-3.6/1.65-5.5V XQFN12; 3D_Mechanical_Footprint_File: http://fcl.am.freescale.net/ALLEGRO/step/xqfn12_0p4_1p8x2p1.step; AGILE_PN: 312-81869; CAD_APPROVED: Yes; HEIGHT: 0.5; MFG_NAME01: NXP SEMICONDUCTORS; ROHS: Yes; Temp Range: -40C to +125C; VOLTAGE: 1.2-3.6/1.65-5.5V
BT1 = BATTERY_SKT_3V: BATTERY RETAINER COIN CELL 6.8MM SMT; 3D_Mechanical_Footprint_File: http://fcl.am.freescale.net/ALLEGRO/step/batt_6p8mm_sm.STEP; AGILE_PN: TMP-CIP-15623; CAD_APPROVED: Yes; HEIGHT: 3.18MM; MFG_NAME01: KEYSTONE ELECTRONICS; PRE_APN: 801-77548; Package Type: PCB, Surface Mount; ROHS: Yes
C6 C15 C43 = CAP_NP: CAP CER 1uF 16V 10% X5R 0402; AGILE_PN: 150-78973; CAD_APPROVED: Yes; FPLIST: CC0402_25,CC0402_HD,0402_CC,capc0402_l; HEIGHT: 0.55 MM; MFG_NAME01: TDK; MFG_PN01: C1005X5R1C105K; ROHS: Yes; Rated Voltage: 16V; Temp Range: -55C to +85C; Tolerance: 10%; VOLTAGE: 16V; voltage rating: 16V
C23 = CAP_NP: CAP CER 47uF 10V 20% X5R 0805; AGILE_PN: 150-78979; CAD_APPROVED: Yes; FPLIST: CC0805_OV,CC0805,0805_CC; HEIGHT: 1.45 MM; MFG_NAME01: TDK; MFG_PN01: C2012X5R1A476M125AC; ROHS: Yes; Rated Voltage: 10V; Temp Range: -55C to +85C; Tolerance: 20%; VOLTAGE: 10V
C25 = CAP_NP: CAP CER 0.1UF 25V 10% X5R 0402; AGILE_PN: 150-78633; CAD_APPROVED: Yes; EN: 102-1-02300; FPLIST: CC0402_25,CC0402_HD,0402_CC,capc0402_l; HEIGHT: 0.55MM; MFG_NAME01: YAGEO AMERICA; MFG_PN01: CC0402KRX5R8BB104; Package Size: 0402; ROHS: Yes; Rated Voltage: 25V; Temp Range: -55C to +85C; Tolerance: 10%; VOLTAGE: 25V
C27 C28 = CAP_NP: CAP CER 56PF 50V 5% C0G 0402; AGILE_PN: 150-80332; CAD_APPROVED: Yes; FPLIST: CC0402_25,CC0402_HD,0402_CC; HEIGHT: 0.55MM; MFG_NAME01: KEMET; MFG_PN01: C0402C560J5GAC; Package Size: 0402; ROHS: Yes; Rated Voltage: 50V; Temp Range: -55C to +125C; Tolerance: 5%; VOLTAGE: 50V
C38 C39 = CAP_NP: CAP CER 56PF 50V 5% C0G 0402; AGILE_PN: 150-80332; CAD_APPROVED: Yes; FPLIST: CC0402_25,CC0402_HD,0402_CC,capc0402_l; HEIGHT: 0.55MM; MFG_NAME01: KEMET; MFG_PN01: C0402C560J5GAC; Package Size: 0402; ROHS: Yes; Rated Voltage: 50V; Temp Range: -55C to +125C; Tolerance: 5%; VOLTAGE: 50V
D2 = ESD_DIODE_2LINE: DIODE BIDIR CAN BUS ESD PROTECTION 2.6A 24V AEC-Q101 SOT23; 3D_Mechanical_Footprint_File: http://fcl.am.freescale.net/ALLEGRO/step/sot23_a.STEP; AGILE_PN: 480-80386; CAD_APPROVED: Yes; HEIGHT: 1.1; MFG_NAME01: Nexperia; MFG_PN01: PESD2CANFD24V-TR; Package Size: TO-236-3, SC-59, SOT-23-3; Rated Voltage: 24V; Temp Range: -55°C to +175°C
D3 = DIODE_SCHTKY: DIODE SCH 30V 200MA -- SOD323; AGILE_PN: 480-30039; CAD_APPROVED: Yes; HEIGHT: 1.15; MFG_NAME01: ON SEMICONDUCTOR; MFG_PN01: BAT54HT1G
J2 = CONN_HDR_4X1: CON 1X4 SHRD TH 2MM SP 303H SN 126L; 3D_Mechanical_Footprint_File: http://www.hxdy.com/NewProductsLook.asp?id=18; AGILE_PN: 210-82576; CAD_APPROVED: Yes; HEIGHT: 7.7; MFG_NAME01: HONGXING ELECTRICAL; MFG_PN01: HX20020-4A; ROHS: Yes; Temp Range: -25 to +85°C
L3 = DLW43: IND CHK 51uH@1MHZ 230mA -30%/+50% 1812; 3D_Mechanical_Footprint_File: http://fcl.am.freescale.net/ALLEGRO/step/IND_DLW43.STEP; AGILE_PN: 180-78178; ASSY_OPT: DNP; CAD_APPROVED: Yes; HEIGHT: 2.8; MFG_NAME01: MURATA; ROHS: Yes
L4 = DLW43: IND CHK 100uH@100KHz 150mA +50/-30% AEC-Q200 SMT; AGILE_PN: 180-79015; CAD_APPROVED: Yes; HEIGHT: 2.4; MFG_NAME01: SHENZHEN SUNLORD ELECTRONICS CO., LTD; MFG_PN01: AMCW3225F-2-101T; PART_TYPE: CHOKE; ROHS: Yes; Temp Range: -40°C ~ 150°C; Temp_Range: -40°C ~ 150°C; VOLTAGE: 50V
R15 R16 = RES: RES MF ZERO OHM 1/16W 5% 0402; AGILE_PN: 470-75394; CAD_APPROVED: Yes; FPLIST: RC0402_25,RC0402_HD,RC0402_X2,0402_CC; HEIGHT: 0.45; MFG_NAME01: YAGEO AMERICA; MFG_PN01: RC0402JR-070RL; RATING: 1/16W; ROHS: Yes; Temp Range: -55 to +155C; Tolerance: 5%; VOLTAGE: 1/16W
R19 = RES: RES MF 330 OHM 1/16W 5% 0402; AGILE_PN: 470-75613; CAD_APPROVED: Yes; FPLIST: RC0402_25,RC0402_HD,0402_CC; HEIGHT: 0.41mm; MFG_NAME01: VISHAY INTERTECHNOLOGY; MFG_PN01: CRCW0402330RJNEA; ROHS: Yes; Tolerance: 5%
R43 R44 = RES: RES MF 62.0 OHM 1/8W 1% AEC-Q200 0603; AGILE_PN: 470-77889; CAD_APPROVED: Yes; FPLIST: RC0603_OV,RC0603,0603_CC; HEIGHT: 0.55MM; MFG_NAME01: KOA SPEER; MFG_PN01: RK73H1JTTD62R0F; ROHS: Yes; Temp Range: -55C to +155C; Tolerance: 1%
R46 = RES: RES MF 1.0K 1/16W 5% 0402; AGILE_PN: 470-75555; CAD_APPROVED: Yes; FPLIST: RC0402_25,RC0402_HD,RC0402_X2,0402_CC; HEIGHT: 0.41mm; MFG_NAME01: VISHAY INTERTECHNOLOGY; MFG_PN01: CRCW04021K00JNED; RATING: 1/16W; ROHS: Yes; Tolerance: 5%
S1 = SW-SPST_A: SW DIP 1 POS 0.025A@24VDC SMT; 3D_Mechanical_Footprint_File: ftp://fcl.am.freescale.net/ALLEGRO/step/sw_2p8x5p7_sm.step; AGILE_PN: 510-78408; CAD_APPROVED: Yes; HEIGHT: 2.5MM; MFG_NAME01: Nidec Copal Electronics Corporation; ROHS: Yes; Temp Range: -40C ~ 85C
U8 = TJA1057GT3_8P: IC XCVR CAN 4.75-5.25V/2.95-5.25V AEC-Q100 SO8; 3D_Mechanical_Footprint_File: http://fcl.am.freescale.net/ALLEGRO/step/so8_1p27_4x5.step; AGILE_PN: 312-81479; CAD_APPROVED: Yes; HEIGHT: 1.75; MFG_NAME01: NXP SEMICONDUCTORS; ROHS: Yes; VOLTAGE: 4.75-5.25V/2.95-5.25V
U12 = PCF2131_A: IC RTC CALENDAR W/XTAL TCXO 3.3V AEC-Q100 HLSON16; 3D_Mechanical_Footprint_File: http://fcl.am.freescale.net/ALLEGRO/step/so16_0p5_3p5x4p5_mm.STEP; AGILE_PN: 312-82330; CAD_APPROVED: Yes; HEIGHT: 1.5mm; MFG_NAME01: NXP SEMICONDUCTORS; Package Size: 3.5 x 4.5 x 1.45 mm; ROHS: NULL; Temp Range: -40°C to 85°C

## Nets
GND: BH3.1 BT1.3(neg) C6.2 C7.2 C15.2 C18.2 C23.2 C24.2 C25.2 C27.1 C28.2 C30.2 C33.2 C34.2 C38.2 C39.2 C43.2 C98.2 C99.2 C100.2 C103.2 C158.2 C167.2 C178.2 C179.2 C185.2 C186.2 C190.2 C191.2 C307.2 C308.2 C309.2 C310.2 D2.3(COM_CATHODE) GND1.1(TP) J2.4 J8.1(GND1) J8.7(GND2) J8.18(GND3) J8.33(GND5) J8.39(GND4) J8.45(GND6) J8.51(GND7) J8.57(GND8) J8.63(GND9) J8.69(GND10) J8.75(GND11) Q9.2(SOURCE) R82.1 R83.1 R114.2 R269.2 R272.2 R273.1 R310.2 R315.2 U8.2(GND) U11.A2(GND) U11.B1(A0) U12.7(VSS) U12.17(GND) U32.10(GND) U41.6(GND) U43.6(GND) U44.6(GND) ; also on sheet 1 2 3 7 8 9 10 11 12 13 17 18 19 23 24
VBUS1_DET_3V3: R113.1 U1.B3(USB1_VBUS)
VDD_1V8: C167.1 C308.1 C310.1 R325.1 R326.1 R327.1 R328.1 R345.2 R386.1 R387.1 U41.1(VREF_A) U43.1(VCCA) U44.1(VCCA) ; also on sheet 2 7 10 11 19 23 24
VDD_3V3: C33.1 C34.1 C43.1 C158.1 C307.1 C309.1 R20.1 R42.1 R76.1 R81.1 R84.1 R87.1 R88.1 R93.1 R94.1 R163.1 R276.1 R290.1 R291.1 R292.1 R293.1 R405.1 R408.1 U8.5(VIO) U11.A1(VCC) U41.11(VREF_B) U43.11(VCCB) U44.11(VCCB) ; also on sheet 1 2 7 8 9 10 11 12 13 19 23 24
VDD_5V: C6.1 C7.1 C15.1 C18.1 J2.1 U8.3(VCC) ; also on sheet 11 12 23
VDD_COIN_3V: BT1.1(pos1) BT1.2(pos2) R46.2 R47.1
VDD_RTC_3V3: C23.1 C24.1 R19.2 U12.15(VDD)
VDD_VBAT_3V: C30.1 R47.2 U12.16(VBAT)
VEN_SPI_CS/1V8: J8.64(RESERVED) R344.1 R345.1
CAN1_RX: R15.1 TP4.1(TP) ; also on sheet 13
CAN1_TX: R16.1 TP5.1(TP) ; also on sheet 13
CAN_H: C27.2 D2.1(CATHODE1) J2.2 L3.2 L4.3 R43.2
CAN_L: C28.1 D2.2(CATHODE2) J2.3 L3.3 L4.2 R44.1
CAN_RX: R15.2 U8.4(RXD)
CAN_STBY: R76.2 U8.8(S) ; also on sheet 13
CAN_TX: R16.2 U8.1(TXD)
CANH: L3.1 L4.4 U8.7(CANH)
CANL: L3.4 L4.1 U8.6(CANL)
DCDC_5V: C100.1 C103.1 R277.1 U32.8(VIN1) U32.11(VIN2) ; also on sheet 2 11 12
ENET1_MDC: U1.T8(ENET1_MDC) ; also on sheet 10
ENET1_MDIO: U1.U7(ENET1_MDIO) ; also on sheet 10
ENET1_nINT: U1.D14(UART2_RXD) ; also on sheet 10
ENET1_RD0: U1.U5(ENET1_RD0) ; also on sheet 10
ENET1_RD1: U1.T6(ENET1_RD1) ; also on sheet 10
ENET1_RD2: U1.U6(ENET1_RD2) ; also on sheet 10
ENET1_RD3: U1.T7(ENET1_RD3) ; also on sheet 10
ENET1_RX_CTL: U1.T5(ENET1_RX_CTL) ; also on sheet 10
ENET1_RXC: U1.U4(ENET1_RXC) ; also on sheet 10
ENET1_TD0: U1.U9(ENET1_TD0) ; also on sheet 10
ENET1_TD1: U1.R9(ENET1_TD1) ; also on sheet 10
ENET1_TD2: U1.U10(ENET1_TD2) ; also on sheet 10
ENET1_TD3: U1.T10(ENET1_TD3) ; also on sheet 10
ENET1_TX_CTL: U1.T9(ENET1_TX_CTL) ; also on sheet 10
ENET1_TXC: U1.U8(ENET1_TXC) ; also on sheet 10
EXT1_PWREN: R279.1 R480.2 ; also on sheet 13
GPIO_IO00: U1.B16(GPIO_IO00) ; also on sheet 23
GPIO_IO01: U1.B17(GPIO_IO01) ; also on sheet 23
GPIO_IO02: U1.C16(GPIO_IO02) ; also on sheet 23
GPIO_IO03: U1.C17(GPIO_IO03) ; also on sheet 23
GPIO_IO04: U1.D16(GPIO_IO04) ; also on sheet 23
GPIO_IO05: U1.D17(GPIO_IO05) ; also on sheet 23
GPIO_IO06: U1.E16(GPIO_IO06) ; also on sheet 23
GPIO_IO07: U1.E17(GPIO_IO07) ; also on sheet 23
GPIO_IO08: U1.K14(GPIO_IO08) ; also on sheet 13
GPIO_IO09: U1.F16(GPIO_IO09) ; also on sheet 13
GPIO_IO10: U1.F17(GPIO_IO10) ; also on sheet 13
GPIO_IO11: U1.G16(GPIO_IO11) ; also on sheet 13
GPIO_IO12: U1.F14(GPIO_IO12) ; also on sheet 23
GPIO_IO13: U1.G17(GPIO_IO13) ; also on sheet 23
GPIO_IO14: U1.H16(GPIO_IO14) ; also on sheet 23
GPIO_IO15: U1.H17(GPIO_IO15) ; also on sheet 23
GPIO_IO16: U1.J16(GPIO_IO16) ; also on sheet 23
GPIO_IO17: U1.K15(GPIO_IO17) ; also on sheet 23
GPIO_IO18: U1.M14(GPIO_IO18) ; also on sheet 23
GPIO_IO19: U1.J17(GPIO_IO19) ; also on sheet 23
GPIO_IO20: U1.K16(GPIO_IO20) ; also on sheet 23
GPIO_IO21: U1.K17(GPIO_IO21) ; also on sheet 23
I2C1_SCL: R94.2 R292.2 R419.1 TP168.1(TP) U41.8(B3) ; also on sheet 12 13
I2C1_SCL_1V8: R327.2 R347.2 U41.4(A3)
I2C1_SDA: R93.2 R293.2 R420.1 TP164.1(TP) U41.7(B4) ; also on sheet 12 13
I2C1_SDA_1V8: R328.2 R348.2 U41.5(A4)
I2C2_SCL: R87.2 TP42.1(TP) U1.A11(I2C2_SCL) ; also on sheet 13 19
I2C2_SDA: R88.2 TP41.1(TP) U1.B11(I2C2_SDA) ; also on sheet 13 19
I2C/I3C1_SCL: R406.2 R419.2 U1.A12(I2C1_SCL)
I2C/I3C1_SDA: R407.2 R420.2 U1.B12(I2C1_SDA)
I3C1_SCL: R405.2 R406.1 TP17.1(TP) U11.B2(SCL)
I3C1_SDA: R407.1 R408.2 TP16.1(TP) U11.C2(SDA)
i.MX_SPI_CLK: R351.2 U43.3(A2)
i.MX_SPI_CS: R324.2 U43.2(A1)
i.MX_SPI_MISO: R352.2 U43.4(A3)
i.MX_SPI_MOSI: R353.2 U43.5(A4)
M2_32K_IN: Q9.1(GATE) R146.1 R157.1
M2_ALERT_B: R326.2 R346.2 U41.3(A2)
M2_ALT_B: J8.62(~{ALERT}) R346.1
M2_I2C_SCL: J8.60(I2C_CLK) R347.1
M2_I2C_SDA: J8.58(I2C_DATA) R348.1
M2_LED1#: D27.C(CATHODE) J8.6(~{LED1})
M2_LED2#: D26.C(CATHODE) J8.16(~{LED2})
M2_LS_OE: R314.1 R315.1 U41.12(EN) U43.12(OE)
M2_nALERT: R291.2 U41.9(B2) ; also on sheet 13
M2_nDIS1: J8.56(~{W_DISABLE1}) R286.1 ; also on sheet 13
M2_nDIS2: J8.54(~{W_DISABLE2}) R310.1 R316.2 ; also on sheet 13
M2_PCM_CLK: J8.8(I2S_SCK) R358.2
M2_PCM_IN: J8.12(I2S_SD_IN) R356.2
M2_PCM_OUT: J8.14(I2S_SD_OUT) R355.2
M2_PCM_SYNC: J8.10(I2S_WS) R357.2
M2_PWRON: R272.1 R276.2 R279.2 R286.2 U32.5(EN)
M2_SAI1_RXD0: U44.9(B2) ; also on sheet 13
M2_SAI1_TXC: U44.7(B4) ; also on sheet 13
M2_SAI1_TXD0: U44.10(B1) ; also on sheet 13
M2_SAI1_TXFS: U44.8(B3) ; also on sheet 13
M2_SD_CLK: J8.9(SDIO_CLK) TP183.1(Pin1) ; also on sheet 13
M2_SD_CMD: J8.11(SDIO_CMD) R387.2 TP181.1(Pin1) ; also on sheet 13
M2_SD_DATA0: J8.13(SDIO_DATA0) R386.2 TP180.1(Pin1) ; also on sheet 13
M2_SD_DATA1: J8.15(SDIO_DATA1) ; also on sheet 13
M2_SD_DATA2: J8.17(SDIO_DATA2) ; also on sheet 13
M2_SD_DATA3: J8.19(SDIO_DATA3) ; also on sheet 13
M2_SD_nWAKE: J8.21(~{SDIO_WAKE}) R325.2 TP179.1(Pin1) U41.2(A1)
M2_UART_nWAKE: J8.20(~{UART_WAKE}) R354.2 ; also on sheet 13
M2_USB_DN: J8.5(USB_D-) TP184.1(Pin1)
M2_USB_DP: J8.3(USB_D+) TP182.1(Pin1)
NVCC_SD2: R151.1 R173.1 R312.1 ; also on sheet 2 17 24
PDM_CLK: U1.A16(PDM_CLK) ; also on sheet 13
PDM_DATA0: U1.A10(PDM_BIT_STREAM0) ; also on sheet 13
PDM_DATA1: U1.B10(PDM_BIT_STREAM1) ; also on sheet 13
PERST: J8.52(~{PERST0}) R480.1
PMIC_32K_OUT: R157.2 ; also on sheet 19
RTC_CLKO: R146.2 TP25.1(Pin1) U12.6(CLKOUT)
RTC_nINTA: R20.2 TP9.1(Pin1) U12.13(~{INTA}) ; also on sheet 13
RTC_SCL: R80.2 R81.2 U12.2(SCL)
RTC_SDA: R84.2 R85.2 U12.5(SDA/~{CE})
SAI1_RXD0: U1.B14(SAI1_RXD0) ; also on sheet 13
SAI1_TXC: U1.B15(SAI1_TXC) ; also on sheet 13
SAI1_TXD0: U1.A15(SAI1_TXD0) ; also on sheet 1 13
SAI1_TXFS: U1.A14(SAI1_TXFS) ; also on sheet 1 13
SAI3_TX_SYNC: U1.D12(UART2_TXD) ; also on sheet 1 23
SD1_CLK: U1.U11(SD1_CLK) ; also on sheet 24
SD1_CMD: U1.T11(SD1_CMD) ; also on sheet 24
SD1_DATA0: U1.T13(SD1_DATA0) ; also on sheet 24
SD1_DATA1: U1.T14(SD1_DATA1) ; also on sheet 24
SD1_DATA2: U1.T15(SD1_DATA2) ; also on sheet 24
SD1_DATA3: U1.U13(SD1_DATA3) ; also on sheet 24
SD1_DATA4: U1.T12(SD1_DATA4) ; also on sheet 24
SD1_DATA5: U1.U14(SD1_DATA5) ; also on sheet 24
SD1_DATA6: U1.U15(SD1_DATA6) ; also on sheet 24
SD1_DATA7: U1.U16(SD1_DATA7) ; also on sheet 24
SD1_STROBE: U1.U12(SD1_STROBE) ; also on sheet 24
SD2_CLK: U1.M16(SD2_CLK) ; also on sheet 24
SD2_CMD: R151.2 U1.M17(SD2_CMD) ; also on sheet 24
SD2_DATA0: R173.2 U1.N17(SD2_DATA0) ; also on sheet 24
SD2_DATA1: U1.N16(SD2_DATA1) ; also on sheet 24
SD2_DATA2: U1.L17(SD2_DATA2) ; also on sheet 24
SD2_DATA3: U1.L16(SD2_DATA3) ; also on sheet 24
SD2_nCD: U1.P12(SD2_CD_B) ; also on sheet 24
SD2_nRST: R312.2 U1.P10(SD2_RESET_B) ; also on sheet 19
SD2_VSEL: U1.P14(SD2_VSELECT) ; also on sheet 19
SD3_CLK: U1.T16(SD3_CLK) ; also on sheet 13
SD3_CMD: U1.T17(SD3_CMD) ; also on sheet 13
SD3_DATA0: U1.R16(SD3_DATA0) ; also on sheet 13
SD3_DATA1: U1.R17(SD3_DATA1) ; also on sheet 13
SD3_DATA2: U1.P16(SD3_DATA2) ; also on sheet 13
SD3_DATA3: U1.P17(SD3_DATA3) ; also on sheet 13
SD3_nRST: J8.23(~{SDIO_RST}) TP178.1(Pin1) ; also on sheet 13
SD3_nWAKE: R290.2 U41.10(B1) ; also on sheet 13
SPI3_CLK: U43.9(B2) ; also on sheet 13
SPI3_CS0: U43.10(B1) ; also on sheet 13
SPI3_MISO: U43.8(B3) ; also on sheet 13
SPI3_MOSI: U43.7(B4) ; also on sheet 13
SUSCLK: J8.50(SUSCLK) R349.1
SUSCLK_32K: Q9.3(DRAIN) R349.2 R350.2
TEMP_nINT: R42.2 TP14.1(Pin1) U11.C1(~{ALERT})
UART1_RXD: U1.B13(UART1_RXD) ; also on sheet 7
UART1_TXD: U1.A13(UART1_TXD) ; also on sheet 1 7
UART5_CTSI: J8.34(UART_CTS) ; also on sheet 13
UART5_RTSO: J8.36(UART_RTS) ; also on sheet 13
UART5_RXD: J8.22(UART_RXD) ; also on sheet 13
UART5_TXD: J8.32(UART_TXD) ; also on sheet 13
USB1_DN: U1.A4(USB1_D_N) ; also on sheet 11
USB1_DP: U1.B4(USB1_D_P) ; also on sheet 11
USB1_ID: U1.D4(USB1_ID) ; also on sheet 11
USB1_VBUS_3V3: R113.2 ; also on sheet 11
USB_I2C_SCL: R80.1 ; also on sheet 11 12
USB_I2C_SDA: R85.1 ; also on sheet 11 12
VBBS: C25.1 U12.14(BBS)
VEN_SPI_CLK: J8.42(VEN_DEF3) R351.1
VEN_SPI_CS: R324.1 R344.2
VEN_SPI_MISO: J8.40(VEN_DEF2) R352.1
VEN_SPI_MOSI: J8.38(VEN_DEF1) R353.1
VEXT_3V3: C98.1 C99.1 C122.1 C123.2 C178.1 C179.1 C185.1 C186.1 C190.1 C191.1 J8.2(3V3_1) J8.4(3V3_2) J8.72(3V3_3) J8.74(3V3_4) L10.2 R268.1 R314.2 R318.2 R322.2 R350.1 R354.1 TP141.1(TP) U32.2(OUT) ; also on sheet 23
VLDO_3V3: D3.A R19.1 R79.1 ; also on sheet 11 12
WDOG_B: R163.2 U1.H14(WDOG_ANY) ; also on sheet 7 19
N117399431: C38.1 R43.1 S1.2(COMMON)
N117399829: C39.1 R44.2 S1.1(NC)
N117400024: D3.C R46.1
N117400223: R79.2 U12.1(IFS)
N117400330: R82.2 U12.3(SDI)
N117400348: R83.2 U12.4(SDO)
N117400350: TP7.1(Pin1) U12.12(~{INTB})
N117400364: TP24.1(Pin1) U12.8(~{TS1})
N117400372: TP11.1(Pin1) U12.9(~{TS2})
N117400380: TP8.1(Pin1) U12.10(~{TS3})
N117400386: TP10.1(Pin1) U12.11(~{TS4})
N117426825: R114.1 U1.A3(USB1_TXRTUNE)
N117456939: L10.1 U32.1(SW1) U32.9(SW2)
N117457136: C122.2 R268.2 R269.1 U32.3(FB)
N117457322: R273.2 R277.2 U32.6(MODE/VCON)
N117457326: C123.1 U32.4(RAMP)
N117457386: TP142.1(Pin1) U32.7(PG)
N117457835: D27.A(ANODE) R318.1
N117457859: R355.1 U44.2(A1)
N117457920: R356.1 U44.3(A2)
N117457977: R357.1 U44.4(A3)
N117458015: R358.1 U44.5(A4)
N117458076: D26.A(ANODE) R322.1
N117458080: R316.1 U44.12(OE)
N117458344: J8.55(~{PEWAKE0}) TP177.1(Pin1)

Not connected (* = marked no-connect by the designer): J8 35(PET_P0)* 37(PET_N0)* 41(PER_P0)* 43(PER_N0)* 44(COEX3)* 46(COEX2)* 47(REFCLK_P0)* 48(COEX1)* 49(REFCLK_N0)* 53(~{CLKREQ0})* 59(PET_P1)* 61(PET_N1)* 65(PER_P1)* 66(~{PERST1})* 67(PER_N1)* 68(~{CLKREQ1})* 70(~{PEWAKE1})* 71(REFCLK_P1)* 73(REFCLK_N1)*

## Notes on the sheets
sheet 20
- CPU IO/PHY
- #eMMC
- #ENET1
- #M.2/QSPI
- USB Z:90 OHM
- Voltage Range:0~3.3V
- #MicroSD
- PHY
- Note:
- If USB connector is MicroAB or MicroB, USBx_VBUS MUST not be directly connected to the 5V VBUS
  of connector. Instead, this pin must be isloated with an external 30K 1% resistor.
- #IO EXP 40P
- WDOG_B has internal PU, external PU is not needed.
- PU
- External PU is necessary for SD2_RESET_B to enable SD card power as default!
- #SoC PU:
        22K-31K-54K <MIN-TYP-MAX> 1.8V
        27K-31K-43K <MIN-TYP-MAX> 3.3V
- I3C TEMP SENSOR
- #SoC PD:
        22K-31K-52K <MIN-TYP-MAX> 1.8V
        25K-31K-40K <MIN-TYP-MAX> 3.3V
- Note for using I3C:
- 1. The total capacitance loading on the I3C bus must be less than 50 pF, including that of the PCB traces and I3C/I2C devices.
- 2. The routing stubs on SCL/SDA traces should not exceed 1.5 inch, stubs will cause reflections and may lead to glitches on the signal edges.
- 3. Strongly recommend to run SI simulation to check the signal quality of SDA and SCL, as the I3C signals have much faster edges than I2C.
- 4. Avoid using level shifter for I3C devices, improper level shifter might cause the bus malfunction. If the level shifter can't be avoided, must choose
  the part without one-shot circuit, such as LSF0204.
- 5. SCL Rise/Fall Time should be less than 60ns, IO drive strength can be adjusted to achieve this.
- 6. For I3C application, external pull-up resistors on SCL and SDA are not needed, the I3C controller is equipped with internal pull-up resistors.
- OD
- 7. It is recommended that only I3C devices are connected to the I3C bus. If both I3C and I2C devices are connected to the bus, make sure that the I2C
  devices are equipped with 50ns Spike Filter, otherwise the I3C bus max frequency will be limited to FM(400KHz)/FM+(1MHz).
- #I2C ADDR: 0b'1001000x
- Put the temp sensor close to CPU.
sheet 21
- CAN BUS
- Split termination for RC tee filter
- fc=1/[2*pie*(Rt/2)*Csplit]
- Z:120 OHM
- # Compatible : TJA1051T/3
- Ext. RTC
- RSUP and CSUP: An appropriate RC filter needs to be added to guarantee the chip will
  only see <0.35 V/ms ramp down rate on supply, even if Vdd_in ramp rate is very high.
- RSUP
- CSUP
- Battery Holder
  for MS621FE
- #I2C ADDR: 0b'1010011x
sheet 22
- M.2 KEY-E
- Power
- Level Shifter
- # 3.3V/4A
- Ru
- Vfb=0.6V
- Vout = (Rd+Ru) * Vfb / Rd
- Default power on to support boot from M.2 QSPI
  NOR/NAND card.
- Rd
- # Discharge Resistor: 150 OHM
- VCC(A) <= VCC(B)
- #Second SRC for LS：
- LSF0204RUTR
- NTS0104GU12
- MODE:
    >1.2V PWM
    <0.4V PFM
- M.2 KEY-E
- DIM:  2230
- RSV for WiFi/BT
- # Current Consumption Limit Peak: 2500mA
- WLAN STAT
- #PCM: MASTER/SLAVE SUPPORT
- o
- LS
- i
- BT STAT
- o
- VCC(A) <= VCC(B)
- o
- o
- #Second SRC for LS：
- TXB0104QRUTRQ1
- TXB0304RUTR
- NXB0104GU12
- i
- FXLA0104QFX
- NLSX3014MUTAG
- o
- PI4ULS3V304A
- i
- o
- i
- i/o
- i
- o
- i
- #GPIO_IO08
- # PIN64 has been defined as VIO-1.8V from M.2 4.0
  SPEC, R957 kept as the compatible design
- #GPIO_IO11
- #GPIO_IO09
- #GPIO_IO10
- LS
- APCI0452-P001A
- H:6.85MM
- # Ultra height reserved for M.2 expansion adapter board
- # DEFAULT M.2 MODULE:
- NXP IW61X
- Note:
- Make sure the level shifters are Off before M.2 power is on.
- SPI for 802.15.4
- 2230
- M.2 SCREW
- i.MX91 GPIO8-11
- M.2
- IW61X GPIO12-15
- #GPIO_IO08
- #SPI3_CS
- #UART7_TXD
- PIN64
- #GPIO_IO13
- #SPI_FRM
- #GPIO_IO09
- #SPI3_MISO
- #UART7_RXD
- PIN40
- #GPIO_IO15
- #SPI_TXD
- #GPIO_IO10
- #SPI3_MOSI
- #UART7_CTS <I>
- PIN38
- #GPIO_IO14
- #SPI_RXD
- #GPIO_IO11
- #SPI3_CLK
- #UART7_RTS <O>
- PIN42
- #GPIO_IO12
- #SPI_CLK
- 2230: SDIO/UART/SPI/PCM/I2C for WiFi/BT/802.15.4
